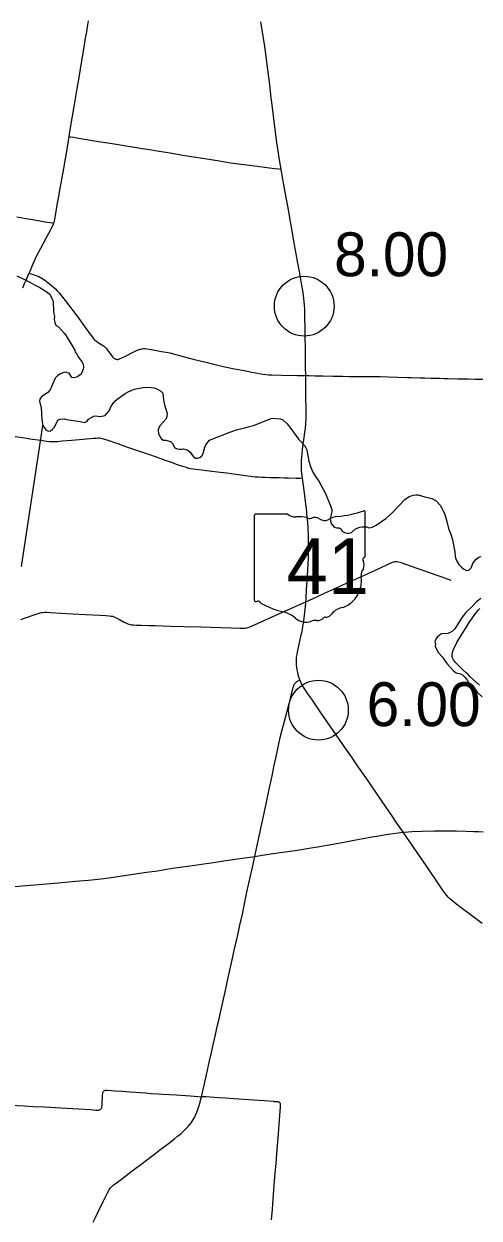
# Model space of a CAD drawing. Extents: x 1597222 to 1925846, y 496284 to 911751.
# Drawn here: x 1697673 to 1709106, y 517019 to 546977 of the extents above; entities that cross this region are included whole.
import ezdxf

# ---------------------------------------------------------------- set-up
doc = ezdxf.new("R2010")
doc.units = 0
for name, color, linetype in [('Default', 7, 'Continuous'), ('GM_X_County_Road', 7, 'Continuous'), ('GM_X_State_Route', 7, 'Continuous'), ('GM_X_State_Shield', 7, 'Continuous'), ('GM_X_Township', 7, 'Continuous'), ('GM_X_Township_Road', 7, 'Continuous')]:
    doc.layers.add(name, color=color, linetype=linetype)

msp = doc.modelspace()

# ---------------------------------------------------------------- linework, layer by layer
at = {"layer": 'Default'}
for centre in [(1704714, 539897), (1704714, 539897), (1705071, 529761), (1705071, 529761)]:
    msp.add_circle(centre, 750, dxfattribs=at)
at = {"layer": 'GM_X_County_Road'}
for points in [[(1697805, 540725), (1697845, 540711), (1697906, 540689), (1697999, 540657), (1698045, 540639), (1698089, 540618), (1698118, 540603), (1698159, 540576), (1698199, 540547), (1698276, 540486), (1698417, 540373), (1698466, 540330), (1698512, 540283), (1698556, 540234), (1698618, 540159), (1698709, 540042), (1698877, 539820), (1699053, 539583), (1699197, 539384), (1699352, 539172), (1699402, 539107), (1699434, 539070), (1699457, 539047), (1699482, 539025), (1699508, 539006), (1699549, 538979), (1699648, 538920), (1699675, 538901), (1699701, 538881), (1699724, 538859), (1699746, 538834), (1699776, 538795), (1699823, 538728), (1699880, 538647), (1699900, 538622), (1699912, 538610), (1699924, 538599), (1699937, 538590), (1699951, 538581), (1699966, 538573), (1699981, 538568), (1699997, 538564), (1700013, 538562), (1700030, 538562), (1700046, 538565), (1700062, 538569), (1700092, 538580), (1700137, 538601), (1700240, 538651), (1700402, 538731), (1700505, 538780), (1700566, 538806), (1700597, 538817), (1700628, 538825), (1700644, 538828), (1700677, 538830), (1700710, 538830), (1700759, 538827), (1700824, 538818), (1700921, 538802), (1701130, 538763), (1701243, 538741), (1701339, 538722), (1701435, 538700), (1701546, 538671), (1701926, 538567), (1702276, 538480), (1702403, 538449), (1702578, 538407), (1702722, 538374), (1702963, 538325), (1703205, 538279), (1703398, 538243), (1703672, 538194), (1703753, 538182), (1703819, 538176), (1703901, 538173), (1704146, 538169), (1704540, 538161), (1704751, 538155)], [(1704751, 538155), (1704785, 538155), (1704834, 538154), (1704982, 538151), (1705179, 538148), (1705441, 538142), (1705687, 538138), (1705851, 538135), (1706048, 538133), (1706212, 538133), (1706409, 538131), (1706622, 538128), (1706819, 538122), (1707065, 538115), (1707311, 538109), (1707393, 538107), (1707622, 538102), (1707737, 538099), (1707901, 538094), (1707999, 538091), (1708114, 538088), (1708228, 538084), (1708326, 538082), (1708572, 538075), (1708835, 538070), (1708999, 538066), (1709196, 538061)], [(1697599, 532035), (1697692, 532067), (1697909, 532144), (1698033, 532187), (1698080, 532201), (1698112, 532208), (1698145, 532213), (1698194, 532217), (1698244, 532217), (1698342, 532212), (1698604, 532195), (1698899, 532178), (1699210, 532162), (1699586, 532142), (1699734, 532135), (1699816, 532129), (1699865, 532123), (1699897, 532116), (1699929, 532106), (1699960, 532094), (1700005, 532073), (1700077, 532034), (1700177, 531978), (1700236, 531950), (1700281, 531931), (1700312, 531920), (1700343, 531911), (1700375, 531905), (1700423, 531899), (1700505, 531895), (1700619, 531892), (1700816, 531887), (1700963, 531883), (1701357, 531872), (1701701, 531861), (1702127, 531848), (1702619, 531832), (1702881, 531824), (1703094, 531817), (1703176, 531816), (1703224, 531819), (1703257, 531823), (1703272, 531826), (1703304, 531834), (1703349, 531850), (1703469, 531903), (1703813, 532059), (1704171, 532221), (1704381, 532315), (1704621, 532421), (1704695, 532455), (1704711, 532461), (1704756, 532482)], [(1709113, 530389), (1709042, 530457), (1708885, 530600), (1708837, 530645), (1708777, 530701), (1708682, 530791), (1708623, 530848), (1708572, 530897), (1708516, 530956), (1708488, 530990), (1708463, 531026), (1708444, 531060), (1708430, 531095), (1708426, 531128), (1708427, 531168), (1708435, 531205), (1708443, 531236), (1708454, 531267), (1708480, 531326), (1708510, 531384), (1708550, 531456), (1708598, 531541), (1708777, 531835), (1708859, 531958), (1708943, 532079), (1709018, 532187), (1709057, 532239), (1709089, 532276), (1709123, 532311)], [(1703470, 526089), (1703487, 526170), (1703580, 526603), (1703687, 527100), (1703746, 527373), (1703842, 527822), (1703880, 527999), (1703914, 528159), (1703951, 528336), (1703976, 528448), (1704006, 528592), (1704076, 528913), (1704112, 529073), (1704152, 529232), (1704185, 529359), (1704243, 529581), (1704285, 529740), (1704327, 529898), (1704357, 530009), (1704390, 530136), (1704420, 530264), (1704434, 530328), (1704443, 530360), (1704449, 530376), (1704456, 530391), (1704463, 530406), (1704472, 530420), (1704482, 530434), (1704493, 530447), (1704504, 530459), (1704517, 530470), (1704530, 530480), (1704544, 530489), (1704607, 530520)], [(1703470, 526089), (1703656, 526121), (1703931, 526162), (1704109, 526189), (1704546, 526253), (1704838, 526297), (1705048, 526331), (1705386, 526392), (1705756, 526461), (1706013, 526512), (1706190, 526546), (1706367, 526577), (1706577, 526611), (1706820, 526648), (1707199, 526700)], [(1707199, 526700), (1707231, 526702), (1707427, 526714), (1707672, 526726), (1707983, 526734), (1708143, 526736), (1708292, 526736), (1708540, 526737), (1708784, 526727), (1708975, 526718), (1709091, 526714), (1709210, 526709)], [(1697349, 525328), (1697839, 525371), (1698444, 525425), (1698721, 525450), (1698966, 525471), (1699293, 525499), (1699457, 525515), (1699685, 525540), (1699864, 525564), (1700415, 525645), (1700756, 525694), (1701032, 525735), (1701210, 525765), (1701404, 525794), (1701599, 525821), (1701843, 525854), (1702022, 525880), (1702135, 525896), (1702379, 525931), (1702590, 525961), (1702979, 526020), (1703222, 526055), (1703417, 526082), (1703470, 526089)], [(1702135, 520064), (1702176, 520243), (1702209, 520387), (1702259, 520611), (1702339, 520963), (1702386, 521171), (1702430, 521363), (1702480, 521587), (1702540, 521860), (1702583, 522052), (1702612, 522180), (1702726, 522692), (1702797, 523013), (1702922, 523573), (1702975, 523813), (1703019, 524005), (1703072, 524246), (1703108, 524406), (1703129, 524502), (1703161, 524646), (1703214, 524903), (1703276, 525192), (1703349, 525528), (1703404, 525785), (1703470, 526089)], [(1697155, 519861), (1697679, 519836), (1697909, 519823), (1698187, 519807), (1698466, 519793), (1698891, 519769), (1699055, 519760), (1699350, 519741), (1699481, 519731), (1699530, 519729), (1699547, 519729), (1699563, 519732), (1699579, 519736), (1699593, 519743), (1699606, 519753), (1699616, 519765), (1699624, 519779), (1699630, 519795), (1699633, 519811), (1699637, 519844), (1699640, 519893), (1699650, 520090), (1699654, 520156), (1699657, 520172), (1699662, 520188), (1699670, 520201), (1699680, 520213), (1699695, 520221), (1699711, 520224), (1699727, 520226), (1699760, 520226), (1699874, 520218), (1699956, 520212), (1700136, 520200), (1700333, 520187), (1700480, 520177), (1700725, 520160), (1700872, 520149), (1701052, 520137), (1701167, 520130), (1701331, 520119), (1701494, 520108), (1701854, 520083), (1702135, 520064)], [(1699417, 516919), (1699481, 517053), (1699531, 517156), (1699676, 517450), (1699726, 517554), (1699777, 517657), (1699808, 517715), (1699825, 517743), (1699844, 517770), (1699865, 517796), (1699888, 517820), (1699912, 517842), (1699964, 517883), (1700122, 518000), (1700397, 518208), (1700608, 518365), (1700751, 518474), (1700922, 518602), (1701079, 518720), (1701341, 518918), (1701457, 519009), (1701533, 519071), (1701621, 519145), (1701694, 519211), (1701752, 519268), (1701797, 519315), (1701840, 519365), (1701879, 519417), (1701907, 519458), (1701933, 519499), (1701956, 519542), (1701985, 519601), (1702016, 519676), (1702051, 519768), (1702077, 519846), (1702100, 519924), (1702121, 520004), (1702135, 520064)], [(1703896, 516976), (1703915, 517238), (1703922, 517369), (1703948, 517729), (1703977, 518056), (1704008, 518399), (1704038, 518743), (1704059, 519021), (1704100, 519595), (1704118, 519807), (1704120, 519840), (1704121, 519857), (1704120, 519873), (1704117, 519889), (1704111, 519904), (1704100, 519916), (1704086, 519924), (1704071, 519930), (1704055, 519933), (1703956, 519940), (1703940, 519942), (1703710, 519958), (1703317, 519985), (1702957, 520011), (1702728, 520028), (1702564, 520038), (1702351, 520052), (1702252, 520058), (1702171, 520062), (1702135, 520064)]]:
    msp.add_lwpolyline(points, dxfattribs=at)
at = {"layer": 'GM_X_State_Route'}
for points in [[(1704754, 537970), (1704751, 538155), (1704748, 538369), (1704746, 538664), (1704742, 538861), (1704739, 539091), (1704734, 539238), (1704734, 539353), (1704730, 539599), (1704726, 539813), (1704722, 539927), (1704716, 540009), (1704707, 540090), (1704685, 540236), (1704655, 540414), (1704591, 540769), (1704554, 540979), (1704513, 541205), (1704456, 541529), (1704402, 541836), (1704370, 542013), (1704325, 542272), (1704214, 542886), (1704154, 543225), (1704134, 543332), (1704102, 543516), (1704075, 543678), (1704058, 543791), (1704029, 544003), (1703970, 544458), (1703907, 544947), (1703886, 545126), (1703849, 545452), (1703786, 545957), (1703745, 546282), (1703726, 546412), (1703692, 546623), (1703620, 547026)], [(1704672, 535587), (1704656, 535701), (1704648, 535783), (1704643, 535865), (1704642, 535948), (1704645, 536030), (1704650, 536096), (1704672, 536297), (1704690, 536430), (1704691, 536439), (1704714, 536600), (1704731, 536726), (1704742, 536833), (1704753, 536941), (1704760, 537089), (1704762, 537286), (1704758, 537647), (1704755, 537926), (1704754, 537970)], [(1704639, 531650), (1704658, 531734), (1704683, 531863), (1704696, 531943), (1704713, 532073), (1704738, 532285), (1704754, 532448), (1704756, 532482), (1704763, 532563), (1704775, 532792), (1704793, 533120), (1704820, 533579), (1704824, 533693), (1704825, 533808), (1704822, 533988), (1704818, 534119), (1704810, 534333), (1704801, 534480), (1704791, 534594), (1704767, 534822), (1704754, 534937), (1704738, 535067), (1704720, 535213), (1704690, 535458), (1704672, 535587)], [(1704972, 529935), (1704901, 530037), (1704804, 530175), (1704746, 530260), (1704698, 530335), (1704649, 530425), (1704630, 530464), (1704607, 530520), (1704580, 530599), (1704565, 530644), (1704551, 530706), (1704544, 530742), (1704537, 530777), (1704529, 530834), (1704523, 530898), (1704521, 530959), (1704521, 531004), (1704522, 531048), (1704524, 531090), (1704534, 531157), (1704545, 531221), (1704568, 531334), (1704639, 531650)], [(1709184, 524406), (1709080, 524486), (1708884, 524634), (1708686, 524780), (1708515, 524908), (1708451, 524958), (1708400, 525001), (1708364, 525034), (1708330, 525070), (1708297, 525108), (1708257, 525159), (1708190, 525253), (1708087, 525401), (1707793, 525836), (1707681, 525998), (1707533, 526214), (1707366, 526457), (1707199, 526700), (1707162, 526755), (1707040, 526930), (1706910, 527120), (1706763, 527337), (1706652, 527499), (1706317, 527986), (1706158, 528215), (1706038, 528391), (1705907, 528579), (1705758, 528795), (1705441, 529254), (1705217, 529578), (1705124, 529713), (1704985, 529916), (1704972, 529935)]]:
    msp.add_lwpolyline(points, dxfattribs=at)
at = {"layer": 'GM_X_State_Shield'}
for p, q in [((1703457, 534640), (1703457, 532527)), ((1704300, 534676), (1703485, 534676)), ((1706241, 533623), (1706241, 534729)), ((1706241, 533623), (1706241, 533623))]:
    msp.add_line(p, q, dxfattribs=at)
for centre, radius, start, end in [((1705250, 537557), 2953, 275.8445, 288.9065), ((1706211, 534733), 31, 351.8621, 97.738), ((1703489, 534644), 32.3, 98.1301, 188.1301), ((1704494, 534922), 313, 231.6195, 271.1119), ((1704598, 533490), 1123, 80.4867, 94.9883), ((1704853, 534655), 90.3, 219.7921, 297.1024), ((1704985, 534411), 188, 54.4667, 119.1411), ((1705228, 534746), 226, 233.8562, 294.8282), ((1705626, 534031), 594, 97.3462, 120.7689), ((1706234, 533542), 48, 107.944, 210.337), ((1706208, 533619), 33.2, 289.6038, 7.7341), ((1706353, 533161), 210, 136.8065, 186.9296), ((1705929, 533402), 288, 340.033, 23.6496), ((1705415, 533020), 739, 292.3089, 8.9858), ((1703489, 532522), 32.5, 171.9584, 258.3066), ((1703494, 532738), 248, 267.339, 280.6039), ((1703545, 532405), 89.5, 29.7484, 93.2717), ((1704676, 534303), 2132, 240.4129, 257.1985), ((1704040, 531577), 667, 47.1842, 75.836), ((1704761, 532394), 423, 230.7004, 286.2918), ((1705037, 532236), 226, 268.777, 315.5493), ((1705241, 532031), 63.5, 65.7517, 132.6484), ((1705214, 532322), 239, 282.8732, 323.2771), ((1705726, 531933), 404, 94.4031, 142.5768), ((1705006, 531664), 348, 85.6951, 111.2099)]:
    msp.add_arc(centre, radius, start, end, dxfattribs=at)
at = {"layer": 'GM_X_Township'}
for points in [[(1697493, 540661), (1697710, 540557), (1697824, 540502), (1697943, 540431), (1698076, 540365), (1698210, 540279), (1698325, 540194), (1698387, 540073), (1698407, 540018), (1698418, 539756), (1698442, 539633), (1698431, 539581), (1698448, 539473), (1698487, 539412), (1698541, 539374), (1698697, 539207), (1698735, 539153), (1698955, 538795), (1698962, 538743), (1699001, 538691), (1699035, 538622), (1699137, 538490), (1699163, 538436), (1699172, 538370), (1699165, 538318), (1699116, 538194), (1699051, 538145), (1699000, 538118), (1698932, 538100), (1698882, 538105), (1698809, 538218), (1698753, 538233), (1698703, 538239), (1698649, 538224), (1698576, 538189), (1698518, 538146), (1698463, 538088), (1698331, 537797), (1698274, 537734), (1698114, 537618), (1698078, 537566), (1698067, 537512), (1698111, 537341), (1698117, 537227), (1698113, 537171), (1698132, 536982), (1698152, 536906)], [(1697617, 533364), (1698092, 536511), (1698152, 536906), (1698228, 536797), (1698284, 536764), (1698340, 536771), (1698395, 536813), (1698446, 536864), (1698524, 537040), (1698576, 537061), (1698689, 537070), (1698741, 537055), (1699089, 537006), (1699197, 536975), (1699261, 537010), (1699296, 537062), (1699429, 537134), (1699479, 537144), (1699585, 537126), (1699716, 537157), (1699813, 537274), (1699869, 537385), (1699916, 537453), (1699959, 537510), (1700009, 537554), (1700214, 537708), (1700274, 537741), (1700447, 537811), (1700668, 537858), (1700793, 537867), (1700935, 537851), (1700993, 537834), (1701114, 537764), (1701164, 537712), (1701176, 537543), (1701202, 537417), (1701268, 537200), (1701265, 537131), (1701244, 537072), (1701097, 536899), (1701063, 536847), (1701044, 536792), (1701057, 536691), (1701120, 536578), (1701173, 536538), (1701237, 536533), (1701353, 536497), (1701404, 536448), (1701465, 536339), (1701521, 536319), (1701581, 536308), (1701635, 536311), (1701685, 536315), (1701741, 536304), (1701793, 536283), (1701849, 536237), (1701931, 536117), (1701985, 536081), (1702035, 536082), (1702092, 536101), (1702142, 536145), (1702175, 536198), (1702215, 536360), (1702242, 536418), (1702331, 536533), (1702843, 536737), (1703010, 536795), (1703440, 536906), (1703754, 537024), (1703859, 537073), (1703910, 537086), (1704120, 537068), (1704174, 537043), (1704285, 536943), (1704379, 536830), (1704570, 536563), (1704613, 536516), (1704721, 536397), (1704756, 536342), (1704777, 536292), (1704832, 536009), (1704882, 535848), (1704929, 535731), (1704996, 535620), (1705080, 535505), (1705245, 535200), (1705389, 534846), (1705404, 534785), (1705403, 534733), (1705365, 534571), (1705371, 534513), (1705386, 534461), (1705413, 534409), (1705467, 534354), (1705521, 534337), (1705579, 534334), (1705631, 534310), (1705670, 534253), (1705726, 534218), (1705783, 534202), (1705840, 534203), (1705900, 534222), (1706003, 534313), (1706114, 534356), (1706172, 534363), (1706276, 534362), (1706344, 534335), (1706417, 534356), (1706524, 534405), (1706762, 534572), (1706932, 534722), (1707239, 535047), (1707346, 535118), (1707461, 535158), (1707513, 535166), (1707573, 535163), (1707745, 535111), (1707921, 535072), (1708028, 535011), (1708131, 534907), (1708164, 534849), (1708244, 534674), (1708292, 534493), (1708334, 534320), (1708400, 534155), (1708437, 534036), (1708493, 533737), (1708506, 533618), (1708523, 533558), (1708544, 533498), (1708593, 533419), (1708651, 533358), (1708712, 533307), (1708786, 533268), (1708844, 533276), (1708903, 533331), (1708946, 533439), (1708981, 533490), (1709034, 533550), (1709097, 533603), (1709155, 533618)], [(1709148, 532560), (1709037, 532476), (1708931, 532359), (1708773, 532209), (1708677, 532098), (1708495, 531801), (1708436, 531744), (1708380, 531707), (1708319, 531687), (1708161, 531673), (1708108, 531642), (1708056, 531594), (1708015, 531541), (1707994, 531481), (1708010, 531429), (1707999, 531369), (1708053, 531254), (1708087, 531203), (1708184, 531094), (1708296, 530928), (1708462, 530752), (1708530, 530701), (1708641, 530671), (1708693, 530639), (1708747, 530590), (1708794, 530531), (1708831, 530469), (1708992, 530308), (1709039, 530252), (1709068, 530201), (1709181, 530098)]]:
    msp.add_lwpolyline(points, dxfattribs=at)
at = {"layer": 'GM_X_Township_Road'}
for points in [[(1698810, 544152), (1698820, 544207), (1698863, 544466), (1698896, 544660), (1698937, 544902), (1698990, 545209), (1699013, 545355), (1699060, 545630), (1699095, 545840), (1699138, 546099), (1699179, 546341), (1699225, 546616), (1699252, 546777), (1699280, 546956), (1699293, 547053)], [(1698426, 541978), (1698432, 541995), (1698442, 542027), (1698453, 542075), (1698485, 542269), (1698513, 542430), (1698552, 542656), (1698587, 542850), (1698634, 543125), (1698673, 543351), (1698757, 543835), (1698810, 544152)], [(1698810, 544152), (1698835, 544148), (1698917, 544135), (1699046, 544114), (1699548, 544031), (1699839, 543984), (1700146, 543934), (1700502, 543877), (1700648, 543852), (1700777, 543832), (1701069, 543785), (1701344, 543740), (1701619, 543694), (1701878, 543652), (1702217, 543598), (1702590, 543540), (1702816, 543504), (1702995, 543477), (1703336, 543432), (1703970, 543352), (1704079, 543339), (1704134, 543332)], [(1697500, 542134), (1697678, 542104), (1697937, 542061), (1698212, 542015), (1698390, 541984), (1698426, 541978)], [(1697805, 540725), (1697828, 540778), (1697871, 540884), (1697903, 540959), (1697930, 541019), (1697957, 541079), (1697994, 541152), (1698102, 541354), (1698241, 541615), (1698340, 541803), (1698400, 541920), (1698421, 541965), (1698426, 541978)], [(1697649, 540356), (1697692, 540462), (1697729, 540550)], [(1697729, 540550), (1697802, 540718), (1697805, 540725)], [(1697451, 536625), (1697694, 536591), (1697823, 536572), (1698099, 536533)], [(1698099, 536533), (1698249, 536510), (1698314, 536502), (1698363, 536499), (1698413, 536499), (1698511, 536505), (1698642, 536516), (1698870, 536535), (1698968, 536544), (1699164, 536561), (1699426, 536582), (1699491, 536588), (1699540, 536590), (1699573, 536590), (1699605, 536587), (1699637, 536580), (1699700, 536561), (1699778, 536536), (1699856, 536509), (1699948, 536476), (1700057, 536439), (1700134, 536412), (1700351, 536337), (1700676, 536224), (1700831, 536171), (1701110, 536073), (1701218, 536034), (1701372, 535979), (1701527, 535926), (1701636, 535890), (1701745, 535854), (1701808, 535836), (1701856, 535825), (1701921, 535814), (1702067, 535795), (1702327, 535765), (1702604, 535731), (1702767, 535711), (1702881, 535697), (1703238, 535651), (1703368, 535633), (1703482, 535618), (1703564, 535611), (1703646, 535607), (1703727, 535604), (1703859, 535600), (1704088, 535594), (1704219, 535591), (1704317, 535588), (1704514, 535583), (1704579, 535583), (1704629, 535585), (1704672, 535587)], [(1704756, 532482), (1704940, 532566), (1705225, 532694), (1705449, 532796), (1705778, 532945), (1706003, 533047), (1706227, 533149), (1706630, 533333), (1706809, 533417), (1706929, 533470), (1706960, 533482), (1706975, 533486), (1706992, 533489), (1707008, 533491), (1707024, 533491), (1707040, 533490), (1707073, 533484), (1707120, 533471), (1707260, 533422), (1707569, 533312), (1707756, 533248), (1708019, 533156), (1708143, 533113), (1708237, 533081), (1708397, 533026)]]:
    msp.add_lwpolyline(points, dxfattribs=at)

# ---------------------------------------------------------------- texts
at = {"layer": 'Default'}
for s, p in [('8.00', (1705464, 540647)), ('8.00', (1705464, 540647)), ('6.00', (1706282, 529360)), ('6.00', (1706282, 529360))]:
    msp.add_text(s, height=1100, dxfattribs=at).set_placement(p)
at = {"layer": 'GM_X_State_Shield'}
msp.add_text('41', height=1392.2, dxfattribs=at).set_placement((1704272, 532676))

doc.saveas('drawing.dxf')
